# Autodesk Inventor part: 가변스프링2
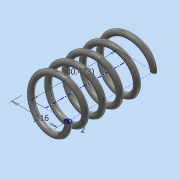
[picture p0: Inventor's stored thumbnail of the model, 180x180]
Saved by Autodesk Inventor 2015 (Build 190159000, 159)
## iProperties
Created: 2018-10
Part Number: 가변스프링2
Material: 스테인레스 스틸
Document SubType Name: Modeling
Designer: SCD-A03
Density: 8 g/cm^3
Appearance: 반연마
Mass: 6.2256 g
Surface Area: 15.8114 cm^2
Volume: 0.778199 cm^3
Author: SCD-A03
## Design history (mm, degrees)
sketch "스케치1"
  geometry: L1 (0, 0)-(8, 0); L2 (8, 0)-(8, 30.473); L3 (8, 30.473)-(0, 30.473); L4 (0, 30.473)-(0, 0); C1 r 1 at (8, 0)
  constraints: 8 end point, 2 parallel, 1 centre point, 1 coincident, 1 horizontal, 1 perpendicular
  dimensions: "d0" = 30.47272 distance of L3.end L1.start (derived); "d1" = 16 diameter of L2 L4; "d2" = 2 diameter of C1
feature "코일1" pitch "d3" = 10; turns "d5" = 5; dims "d4" = 30.47272 (= d0), "d6" = 0, angle "d7" = 90 deg, angle "d8" = 90 deg, "d9" = 0, "d10" = 0
node "작업 평면1"
node "작업 평면2"
sketch "스케치2"
  geometry: L1 (9, 0)-(7, 0) reference; 1 further point
  constraints: 1 horizontal alignment
extrude "돌출1" cut sketch "스케치2" distance "d11" = 10; taper "d12" = 0 deg
sketch "스케치3"
  geometry: L1 (7, 0)-(9, 0) reference; 1 further point
  constraints: 1 horizontal alignment
extrude "돌출2" cut sketch "스케치3" distance "d13" = 10; taper "d14" = 0 deg
node "솔리드1"
node "절단 모서리 투영1"
node "절단 모서리 투영2"
